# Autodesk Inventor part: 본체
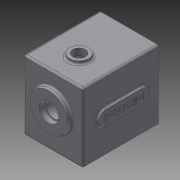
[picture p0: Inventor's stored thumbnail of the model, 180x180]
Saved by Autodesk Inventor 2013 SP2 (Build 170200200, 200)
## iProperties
Created: 2016-02
Part Number: 본체
Material: 일반
Document SubType Name: Modeling
Designer: mduedu
Density: 1 g/cm^3
Author: mduedu
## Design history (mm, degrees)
sketch "스케치1"
  geometry: L1 (-47, -47)-(47, -47); L2 (47, -47)-(47, 63); L3 (47, 63)-(-47, 63); L4 (-47, 63)-(-47, -47); 2 further points
  constraints: 8 end point, 2 parallel, 1 horizontal, 1 midpoint, 1 perpendicular, 1 vertical alignment
  dimensions: "d0" = 94 distance of L2.end L3.end; "d155" = 110 distance of L1.end L2.end; "d156" = 47 distance from line of L1 point (0, 0)
extrude "돌출1" new body sketch "스케치1" distance "d2" = 120; taper "d3" = 0 deg
sketch "스케치3"
  geometry: L1 (47, -47)-(-47, -47) reference; L2 (47, 63)-(47, -47) reference; L3 (-47, 63)-(47, 63) reference; L4 (-47, -47)-(-47, 63) reference; L5 (37, 53)-(37, -37); L6 (37, -37)-(-37, -37); L7 (-37, -37)-(-37, 53); L8 (-37, 53)-(37, 53); 1 further point
  constraints: 8 end point, 3 other
  dimensions: "d226" = 10 distance between parallel lines of L8 L3
extrude "돌출3" cut sketch "스케치3" distance "d11" = 110; taper "d12" = 0 deg
sketch "스케치4"
  geometry: C1 r 21 at (0, 11); 1 further point
  constraints: 1 centre point, 1 vertical alignment
  dimensions: "d13" = 21 radius of C1; "d227" = 11 distance of point (0, 0) C1.centre
extrude "돌출4" join sketch "스케치4" distance "d16" = 7; taper "d17" = 0 deg
sketch "스케치5"
  geometry: C1 r 15 at (0, -20); 1 further point
  constraints: 1 centre point, 1 vertical alignment
  dimensions: "d18" = 15 radius of C1; "d20" = 20 distance of point (0, 0) C1.centre
extrude "돌출5" join sketch "스케치5" distance "d21" = 7; taper "d22" = 0 deg
sketch "스케치6"
  geometry: C1 r 30 at (0, 11); A1 r 21 centre (0, 11) between (8.978, -7.984) and (-8.978, -7.984) reference; 1 further point
  constraints: 1 centre point, 1 coincident
  dimensions: "d228" = 60 diameter of C1
extrude "돌출6" join sketch "스케치6" distance "d25" = 7; taper "d26" = -3 deg
hole "구멍1" diameter "d29" = 30; stored, may be unused: countersink angle "d33" = 90 deg, drill point angle "d35" = 0 deg; dims "d30" = 6, "d31" = 4, "d32" = 2, "d34" = 7, "d269" = 10, "d270" = 10
hole "구멍2" diameter "d38" = 22; stored, may be unused: countersink angle "d42" = 90 deg, drill point angle "d44" = 0 deg; dims "d36" = 10, "d37" = 10, "d39" = 6, "d40" = 4, "d41" = 2, "d43" = 7
hole "구멍3" diameter "d47" = 19; stored, may be unused: countersink angle "d51" = 90 deg, drill point angle "d53" = 0 deg; dims "d45" = 10, "d46" = 10, "d48" = 6, "d49" = 4, "d50" = 2, "d52" = 1
hole "구멍4" diameter "d56" = 30; stored, may be unused: countersink angle "d60" = 90 deg, drill point angle "d62" = 0 deg; dims "d57" = 6, "d58" = 4, "d59" = 2, "d61" = 8.3, "d271" = 10, "d272" = 10
hole "구멍5" diameter "d65" = 26; stored, may be unused: countersink angle "d69" = 90 deg, drill point angle "d71" = 0 deg; dims "d66" = 6, "d67" = 4, "d68" = 2, "d70" = 8, "d267" = 10, "d268" = 10
fillet "모깎기2" dims "d73" = 0.3
fillet "모깎기3" dims "d74" = 2
chamfer "모따기1" distance "d75" = 1; stored, may be unused: second distance "d76" = 2, angle "d77" = 45 deg
fillet "모깎기4" dims "d78" = 3
fillet "모깎기23" dims "d240" = 1
fillet "모깎기20" dims "d229" = 3
sketch "스케치23"
  geometry: L1 (-37, 53)-(37, 53) reference; L2 (37, 53)-(37, -37) reference; L3 (37, -37)-(-37, -37) reference; L4 (-37, -37)-(-37, 53) reference; L5 (44, -47)-(-44, -47) reference; L6 (47, 60)-(47, -44) reference; L7 (-44, 63)-(44, 63) reference; L8 (-47, -44)-(-47, 60) reference; C1 r 10 at (-37, 53); C2 r 10 at (37, 53); C3 r 10 at (-37, -37); C4 r 10 at (37, -37); A1 r 3 centre (-44, -44) between (-47, -44) and (-44, -47) reference; A2 r 3 centre (44, -44) between (44, -47) and (47, -44) reference; A3 r 3 centre (44, 60) between (47, 60) and (44, 63) reference; A4 r 3 centre (-44, 60) between (-44, 63) and (-47, 60) reference; 1 further point
  constraints: 4 centre point, 4 coincident, 3 equal radius
  dimensions: "d230" = 20 diameter of C1
extrude "돌출22" join sketch "스케치23" stored distance "d235" = 10; taper "d236" = 0 deg
fillet "모깎기21" dims "d237" = 3
node "작업 평면1"
fillet "모깎기22" dims "d239" = 1
sketch "스케치12"
  geometry: A1 r 10 centre (-37, 53) between (-34.692, 43.27) and (-27.27, 50.692) reference; A2 r 10 centre (37, 53) between (27.27, 50.692) and (34.692, 43.27) reference; A3 r 10 centre (37, -37) between (34.692, -27.27) and (27.27, -34.692) reference; A4 r 10 centre (-37, -37) between (-27.27, -34.692) and (-34.692, -27.27) reference; 5 further points
  constraints: 4 coincident
hole "구멍6" sketch "스케치12" at (-37, 53), (37, 53), (37, -37), (-37, -37) diameter "d122" = 3.242; stored, may be unused: countersink angle "d126" = 90 deg, drill point angle "d128" = 120 deg; dims "d123" = 7, "d124" = 4, "d125" = 2, "d127" = 9
sketch "스케치20"
  geometry: L1 (44, 0)-(-44, 0) reference; L2 (44, -120)-(-44, -120) reference; L3 (0, 0)-(0, -120); L4 (-44, -120)-(-44, 0) reference; L5 (44, 0)-(44, -120) reference; C1 r 10 at (0, -79)
  constraints: 2 end point, 1 centre point, 1 midpoint, 1 point on line
  dimensions: "d189" = 20 diameter of C1; "d190" = 41 distance from line of C1.centre L2
extrude "돌출19" cut sketch "스케치20" stored distance "d191" = 10; taper "d192" = 0 deg
sketch "스케치18"
  geometry: C1 r 15 at (0, -79); C2 r 10 at (0, -79) reference; 1 further point
  constraints: 1 centre point, 1 concentric
  dimensions: "d174" = 30 diameter of C1
extrude "돌출17" join sketch "스케치18" distance "d175" = 5; taper "d176" = 0 deg
fillet "모깎기16" dims "d177" = 3
sketch "스케치19"
  geometry: C1 r 15 at (24.351, 79); C2 r 10 at (24.351, 79) reference; 1 further point
  constraints: 1 centre point, 1 concentric
  dimensions: "d178" = 30 diameter of C1
extrude "돌출18" cut sketch "스케치19" distance "d181" = 5; taper "d182" = 0 deg
chamfer "모따기5" distance "d183" = 1; stored, may be unused: second distance "d184" = 2, angle "d185" = 45 deg
fillet "모깎기24" dims "d242" = 3, "d243" = 3
sketch "스케치24"
  geometry: L1 (-86, 64)-(-30, 64); L2 (-30, 64)-(-30, 40); L3 (-30, 40)-(-86, 40); L4 (-86, 40)-(-86, 64); L5 (0, 0)-(0, 104) reference; L6 (-86, 52)-(-30, 52); L7 (-58, 64)-(-58, 40); A1 r 12 centre (-86, 52) between (-86, 40) and (-86, 64); A2 r 12 centre (-30, 52) between (-30, 64) and (-30, 40); A3 r 12 centre (-30, 52) between (-30, 40) and (-30, 64); A4 r 12 centre (-86, 52) between (-86, 64) and (-86, 40); 2 further points
  constraints: 12 end point, 8 point on circle, 5 midpoint, 4 centre point, 2 parallel, 2 perpendicular, 1 horizontal, 1 horizontal alignment
  dimensions: "d244" = 58 distance between parallel lines of L7 L5; "d245" = 80 dimension on A2 A1; "d246" = 24 distance between parallel lines of L3 L1
extrude "돌출23" join sketch "스케치24" distance "d247" = 3; taper "d248" = 0 deg
fillet "모깎기25" dims "d249" = 3
sketch "스케치25"
  geometry: L1 (-30, 64)-(-86, 64) reference; L2 (-86, 40)-(-30, 40) reference; A1 r 12 centre (-86, 52) between (-86, 64) and (-86, 40) reference; A2 r 12 centre (-30, 52) between (-30, 40) and (-30, 64) reference; 3 further points
  constraints: 1 horizontal alignment, 1 midpoint, 1 vertical alignment, 1 other
feature "엠보싱3" sketch "스케치25" dims "d32" = 2, "d250" = 0.5, "d251" = 0
sketch "스케치26"
  geometry: L1 (14.367, 127)-(73.633, 127) reference; L2 (0, 0)-(88, 0) reference; L3 (88, 120)-(0, 120) reference; 5 further points
  constraints: 3 vertical alignment, 2 midpoint
  dimensions: "d252" = 35 distance from line of point (44, 35) L2; "d253" = 35 distance from line of point (44, 85) L3; "d254" = 50 distance of point (44, 35) point (44, 85) (derived)
hole "구멍8" sketch "스케치26" at (44, 85), (44, 35) diameter "d255" = 6.647; stored, may be unused: countersink angle "d259" = 90 deg, drill point angle "d261" = 118 deg; dims "d256" = 6, "d257" = 4, "d258" = 2, "d260" = 8
chamfer "모따기7" distance "d262" = 0.8; stored, may be unused: second distance "d263" = 2, angle "d264" = 30 deg
node "솔리드1"
node "투영된 루프1"
node "투영된 루프4"
node "투영된 루프5"
node "투영된 루프6"
